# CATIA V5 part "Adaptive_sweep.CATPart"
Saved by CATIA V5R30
Part number: Part1
Bounding box of the stored display mesh (mm): x -106.531 to 0, y -4.546 to 2.643, z -53.351 to 74.079
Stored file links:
  D:\PROJECTS\CATIA V56R 2020\Resources\Parts File\c17_catia_v6_6r2020_prt\Adaptive_sweep.CATPart
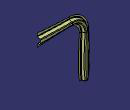
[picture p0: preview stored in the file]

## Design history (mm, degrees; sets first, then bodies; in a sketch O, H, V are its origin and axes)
Body1 (main body)
  Sketch1 on zx-plane, origin (0, 0, 0), H (-1, 0, 0), V (0, 0, 1)
    point P1 (0, 61.5796)
    line L1 (0, 61.5796) -> (65, 61.5796)
    line L2 (94.9999, 31.6495) -> (94.9999, -53.3505)
    point P2 (94.9999, -53.3505)
    arc A1 centre (64.9999, 31.5796) radius 30 from (65, 61.5796) to (94.9999, 31.6495) cw
    radius A1 = 30
    length L1 = 65
    length L2 = 85
    coincidence: P1 V
    horizontal: L1 H
    vertical: L2 V
    tangency: A1 L1, A1 L2
  Sketch2 on {plane type Normal, Curve Sketch1, RefPoint Sketch1.P2}, origin (-94.9999, 0, -53.3505), H (1, 0, 0), V (0, 1, 0)
    point P1 (-5.022, -3.8355)
    line L1 (-4.7817, -3.2105) -> (-2.9, 1.6817)
    point P2 (-2.522, 2.6645)
    line L2 (-5.8642, -3.8355) -> (-8.8642, -3.8355)
    point P3 (-8.8642, -3.8355)
    arc A1 centre (-1.5, 1.1433) radius 1.5 from (-2.9, 1.6817) to (-1.5, 2.6433) cw
    point P4 (-2.9, 1.6817)
    point P5 (-1.5, 2.6433)
    line L3 (-5.8642, -3.8355) -> (-4.7817, -3.2105)
    point P7 (-5.8642, -3.8355)
    point P8 (-4.7817, -3.2105)
    point P9 (5.022, -3.8355)
    point P10 (2.522, 2.6645)
    point P11 (8.8642, -3.8355)
    point P12 (2.9, 1.6817)
    point P13 (1.5, 2.6433)
    point P15 (5.8642, -3.8355)
    point P16 (4.7817, -3.2105)
    line L4 (4.7817, -3.2105) -> (2.9, 1.6817)
    line L5 (5.8642, -3.8355) -> (8.8642, -3.8355)
    arc A2 centre (1.5, 1.1433) radius 1.5 from (2.9, 1.6817) to (1.5, 2.6433) ccw
    line L6 (5.8642, -3.8355) -> (4.7817, -3.2105)
    line L7 (-1.5, 2.6433) -> (1.5, 2.6433)
    distance P2 P1 V = 6.5
    radius A1 = 1.5
    angle L2 L3 = 30
    length L3 = 1.25
    length L2 = 3
    length L7 = 3
    horizontal: L2 H
    coincidence: L1 P2, L2 P1, L1 P1
    tangency: A1 L1, L7 A1
    symmetry: P1 P9 V, P2 P10 V, P3 P11 V, P4 P12 V, P5 P13 V, P7 P15 V, P8 P16 V, L1 L4 V, L2 L5 V, A1 A2 V, L3 L6 V
  SweepSketch1: Spine Sketch1, Sketch Sketch2, ListSketches (a sketch; a sketch; a sketch; a sketch), SectionVertices ({point type OnCurve, Support Sketch1, Ratio 0}; Sketch1.P1; {point type OnCurve, Support Sketch1, Ratio 0.154867}; {point type OnCurve, Support Sketch1, Ratio 0.572067})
